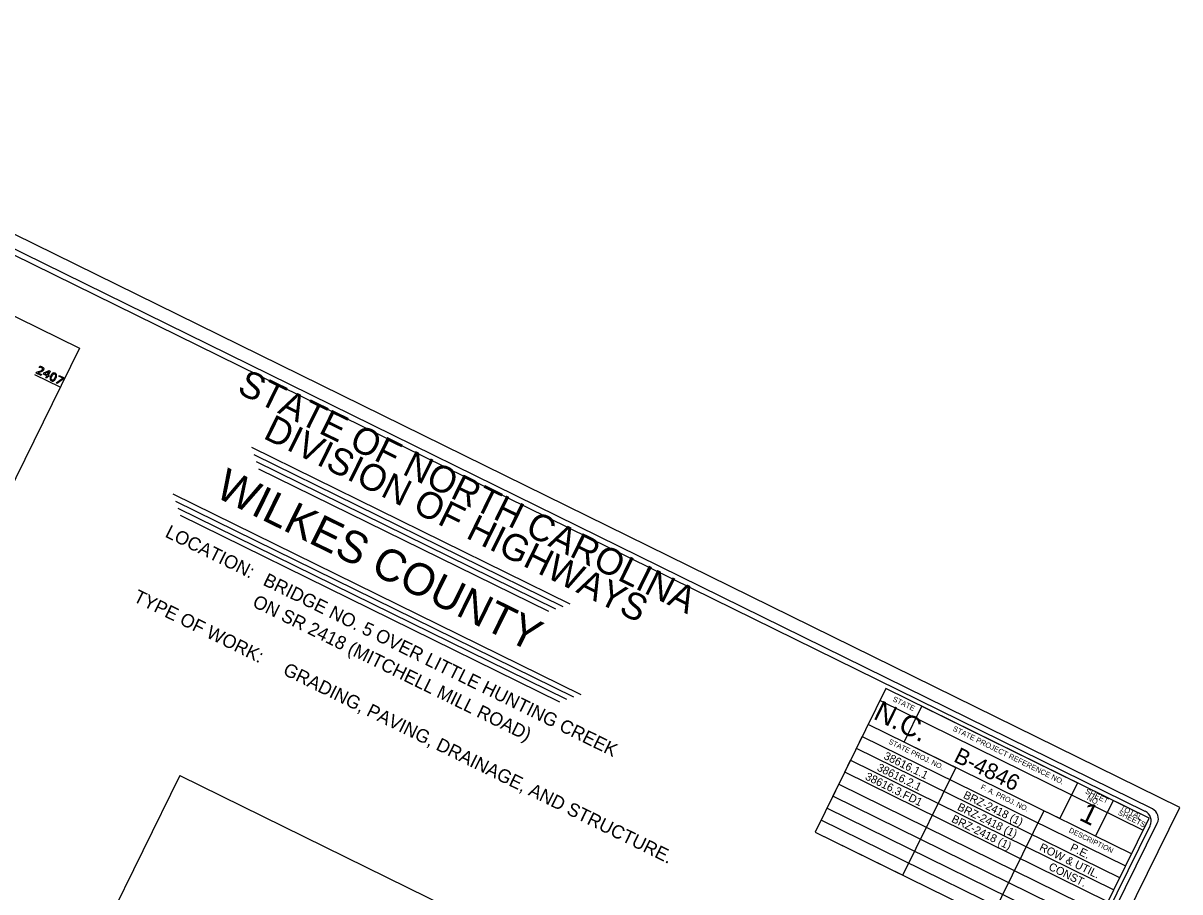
# Model space of a CAD drawing. Extents: x 1428128 to 1430390, y 857947 to 859822.
# Drawn here: x 1429306 to 1430390, y 858882 to 859697 of the extents above; entities that cross this region are included whole.
import ezdxf

# ---------------------------------------------------------------- set-up
doc = ezdxf.new("R2010")
doc.units = 0
for name, color, linetype in [('Old_Level_1', 7, 'Continuous'), ('Sheet Data Field CELL', 7, 'Continuous'), ('Sheet Plot Border Inside CELL', 7, 'Continuous'), ('Sheet Title CELL', 7, 'Continuous')]:
    doc.layers.add(name, color=color, linetype=linetype)

msp = doc.modelspace()

# ---------------------------------------------------------------- linework, layer by layer
at = {"layer": 'Old_Level_1'}
msp.add_line((1429316.3, 859367.2), (1429339.8, 859355.6), dxfattribs=at)
for points in [[(1429322.4, 859366.4), (1429317.9, 859368.6), (1429318.3, 859369.6)], [(1429319.2, 859368.9), (1429322.8, 859367.2), (1429322.4, 859366.4)], [(1429320.8, 859374), (1429320.7, 859374), (1429321.2, 859375)], [(1429329.6, 859365.2), (1429328.6, 859365.7), (1429327.7, 859363.8), (1429326.8, 859364.2), (1429327.7, 859366.1), (1429324.5, 859367.7), (1429325, 859368.8), (1429330.1, 859370.9), (1429331, 859370.5), (1429328.9, 859366.4), (1429329.9, 859365.9), (1429329.6, 859365.2)], [(1429328.1, 859366.9), (1429329.6, 859369.9), (1429325.5, 859368.1), (1429328.1, 859366.9)], [(1429343.5, 859363.1), (1429337.6, 859358.9), (1429336.6, 859359.4), (1429342.8, 859363.7), (1429339, 859365.6), (1429339.3, 859366.4), (1429344, 859364.1), (1429343.5, 859363.1)]]:
    msp.add_lwpolyline(points, dxfattribs=at)
for points in [[(1429318.3, 859369.6), (1429319, 859369.7), (1429319.7, 859369.9), (1429320.4, 859370.1), (1429321, 859370.3), (1429322.3, 859370.7), (1429322.8, 859371), (1429323.4, 859371.4), (1429323.7, 859371.9), (1429323.9, 859372.5), (1429323.7, 859372.9), (1429323.5, 859373.4), (1429322.9, 859373.7), (1429322.5, 859373.9), (1429321.9, 859374), (1429321.4, 859374.1), (1429320.8, 859374)], [(1429321.2, 859375), (1429321.6, 859375), (1429322.2, 859374.9), (1429322.8, 859374.7), (1429323.3, 859374.5), (1429324.4, 859374), (1429324.7, 859373.2), (1429325, 859372.4), (1429324.6, 859371.5), (1429324.4, 859371.2), (1429324.2, 859370.9), (1429323.9, 859370.6), (1429323.6, 859370.4), (1429323.3, 859370.2), (1429322.9, 859370), (1429322.5, 859369.9), (1429322, 859369.7), (1429321.3, 859369.5), (1429320.6, 859369.3), (1429319.8, 859369.1), (1429319.2, 859368.9)], [(1429336.2, 859363.8), (1429335.3, 859362), (1429334.3, 859361.4), (1429333.3, 859360.8), (1429332.2, 859361.4), (1429330.9, 859362), (1429330.8, 859363.1), (1429330.7, 859364.3), (1429331.5, 859366.1), (1429332.4, 859367.9), (1429333.4, 859368.4), (1429334.4, 859369), (1429335.6, 859368.4), (1429336.8, 859367.8), (1429336.9, 859366.7), (1429337.1, 859365.5), (1429336.2, 859363.8)], [(1429334, 859362.3), (1429334.3, 859362.6), (1429334.6, 859363.1), (1429334.9, 859363.5), (1429335.3, 859364.2), (1429335.6, 859364.9), (1429335.8, 859365.5), (1429336, 859366), (1429336, 859366.4), (1429336, 859366.9), (1429335.9, 859367.2), (1429335.7, 859367.5), (1429335.2, 859367.7), (1429334.8, 859367.9), (1429334.4, 859367.9), (1429334.1, 859367.8), (1429333.7, 859367.5), (1429333.4, 859367.3), (1429333.1, 859366.8), (1429332.8, 859366.3), (1429332.5, 859365.6), (1429332.1, 859364.9), (1429331.9, 859364.4), (1429331.8, 859363.9), (1429331.7, 859363.5), (1429331.7, 859363), (1429331.9, 859362.7), (1429332.1, 859362.4), (1429332.5, 859362.2), (1429332.9, 859362), (1429333.3, 859362), (1429333.7, 859362), (1429334, 859362.3)]]:
    msp.add_open_spline(points, degree=3, dxfattribs=at)
at = {"layer": 'Sheet Data Field CELL'}
msp.add_line((1429452.5, 858991.3), (1429957.2, 858742.9), dxfattribs=at)
msp.add_lwpolyline([(1429452.5, 858991.3), (1429278.6, 858638), (1429783.3, 858389.6), (1429957.2, 858742.9)], dxfattribs=at)
at = {"layer": 'Sheet Plot Border Inside CELL'}
msp.add_lwpolyline([(1428428.7, 858750.2), (1429924, 858014.4), (1430389.9, 858961.1), (1428894.6, 859696.9)], close=True, dxfattribs=at)
at = {"layer": 'Sheet Title CELL'}
for p, q in [((1429080.3, 859528.8), (1429358.4, 859391.9)), ((1429358.4, 859391.9), (1429217.1, 859104.8)), ((1429519.5, 859299), (1429818.1, 859152.1)), ((1429521.8, 859292.3), (1429811.4, 859149.8)), ((1429524.1, 859285.6), (1429804.7, 859147.5)), ((1429526.3, 859278.9), (1429798, 859145.2)), ((1429446, 859255.3), (1429828.3, 859067.2)), ((1429448.3, 859248.6), (1429821.6, 859065)), ((1429450.6, 859241.9), (1429814.9, 859062.7)), ((1429452.9, 859235.2), (1429808.2, 859060.4))]:
    msp.add_line(p, q, dxfattribs=at)
for points in [[(1430364.1, 858959.8), (1429036.2, 859613.2)], [(1430357.4, 858957.5), (1429083.3, 859584.4)], [(1430322.4, 858872.7), (1430075.7, 858994.2), (1430081.2, 859005.4), (1430327.9, 858884), (1430333.5, 858895.2), (1430086.7, 859016.6), (1430092.2, 859027.8), (1430339, 858906.4), (1430344.5, 858917.6), (1430097.8, 859039), (1430108.8, 859061.5), (1430355.5, 858940), (1430361.1, 858951.3), (1430114.3, 859072.7), (1430048.1, 858938.1), (1430130.3, 858897.6), (1430180, 858998.5), (1430131.4, 859022.5), (1430148, 859056.1), (1430293.8, 858984.4), (1430277.2, 858950.7), (1430262.2, 858958.1), (1430212.6, 858857.2)], [(1430311.4, 858850.3), (1430064.6, 858971.7), (1430070.2, 858982.9), (1430316.9, 858861.5)], [(1430294.8, 858816.7), (1430361.1, 858951.3), (1430327.4, 858967.8), (1430310.9, 858934.2)], [(1430300.3, 858827.9), (1430053.6, 858949.3), (1430059.1, 858960.5), (1430305.9, 858839.1)], [(1429922.8, 858040.2), (1430368.7, 858946.4)], [(1430002.2, 858212.8), (1430362, 858944.1)], [(1430048.1, 858938.1), (1430294.8, 858816.7)]]:
    msp.add_lwpolyline(points, dxfattribs=at)
for centre in [(1430353, 858948.6), (1430359.7, 858950.8)]:
    msp.add_arc(centre, 10, 333.8001, 63.8001, dxfattribs=at)

# ---------------------------------------------------------------- texts
at = {"layer": 'Sheet Data Field CELL'}
for s, height, p in [('WILKES COUNTY', 30, (1429484, 859253.3)), ('BRIDGE NO. 5 OVER LITTLE HUNTING CREEK', 12.5, (1429529.5, 859170.3)), ('ON SR 2418 (MITCHELL MILL ROAD)', 12.5, (1429519.6, 859150.1)), ('GRADING, PAVING, DRAINAGE, AND STRUCTURE.', 12.5, (1429548.2, 859086.4)), ('38616.1.1', 7.5, (1430111.6, 859007.1)), ('B-4846', 15, (1430176.9, 859004.7)), ('38616.2.1', 7.5, (1430105.3, 858996.2)), ('38616.3.FD1', 7.5, (1430094.2, 858987.8)), ('BRZ-2418 (1)', 7.5, (1430186.1, 858970.4)), ('BRZ-2418 (1)', 7.5, (1430180.6, 858959.2)), ('BRZ-2418 (1)', 7.5, (1430175.1, 858948)), ('ROW & UTIL.', 7.5, (1430257.5, 858921.4)), ('P.E.', 7.5, (1430286.3, 858921.2)), ('CONST.', 7.5, (1430266.1, 858903.2))]:
    msp.add_text(s, height=height, rotation=333.8001, dxfattribs=at).set_placement(p)
at = {"layer": 'Sheet Title CELL'}
for s, height, p in [('STATE OF NORTH CAROLINA', 25, (1429505, 859350.6)), ('DIVISION OF HIGHWAYS', 25, (1429529.6, 859307.9)), ('LOCATION: ', 12.5, (1429437.8, 859215.4)), ('TYPE OF WORK:', 12.5, (1429408, 859154.9)), ('STATE', 5, (1430120.1, 859061.2)), ('N.C.', 19.35, (1430101.5, 859044.8)), ('STATE PROJECT REFERENCE NO.', 5, (1430176.5, 859033.4)), ('STATE PROJ. NO.', 4.8, (1430116.3, 859021.4)), ('F. A. PROJ. NO.', 4.8, (1430202.7, 858978.8)), ('SHEET', 5, (1430300.7, 858974.8)), ('NO.', 5, (1430302.2, 858968.5)), ('1', 19.3, (1430294.5, 858949.9)), ('SHEETS', 5, (1430331.4, 858954.5)), ('TOTAL', 5, (1430333.3, 858959.2)), ('DESCRIPTION', 4.8, (1430285.4, 858938.2))]:
    msp.add_text(s, height=height, rotation=333.8001, dxfattribs=at).set_placement(p)

doc.saveas('drawing.dxf')
